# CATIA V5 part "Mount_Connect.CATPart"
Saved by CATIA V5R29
Part number: Mount_Connect_02
Source: Unknown
Bounding box of the stored display mesh (mm): x -50 to 60, y -45 to 45, z -45 to 45
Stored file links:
  C:\가치같이\SmartFactory_BoxErectorConveyor\Mount_Connect.CATPart
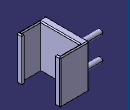
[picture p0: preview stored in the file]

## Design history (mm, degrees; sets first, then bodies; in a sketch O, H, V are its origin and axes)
Body1 (main body)
  Solid1 "PartBody": solid without history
